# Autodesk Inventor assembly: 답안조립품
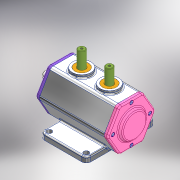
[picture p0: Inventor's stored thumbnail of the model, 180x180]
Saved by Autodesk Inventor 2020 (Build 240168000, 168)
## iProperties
Created: 2021-06
Part Number: 답안조립품
Document SubType Name: Assembly
Designer: Windows7
Author: Windows7
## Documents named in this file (11)
- C:\Users\Windows7\Desktop\710606V1005\답안조립품.iam
- C:\Users\Windows7\Desktop\710606V1005\본체.ipt
- C:\Users\Windows7\Desktop\710606V1005\뒷커버.ipt
- C:\Users\Windows7\Desktop\710606V1005\앞커버.ipt
- C:\Users\Windows7\Desktop\710606V1005\부시.ipt
- C:\Users\Windows7\Desktop\710606V1005\베어링 6203.ipt
- C:\Users\Windows7\Desktop\710606V1005\베어링 6302.ipt
- C:\Users\Windows7\Desktop\710606V1005\오일실.ipt
- C:\Users\Windows7\Desktop\710606V1005\편심축.ipt
- C:\Users\Windows7\Desktop\710606V1005\슬라이더.ipt
- C:\Users\Windows7\Desktop\710606V1005\볼트 M4.ipt
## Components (10 placed, 3 different names)
1. 7-베어링 6203:1
2. 8-오일실:1
3. 9-M4-소켓머리:1
4. 9-M4-소켓머리:3
5. 9-M4-소켓머리:4
6. 9-M4-소켓머리:5
7. 9-M4-소켓머리:2
8. 9-M4-소켓머리:6
9. 9-M4-소켓머리:7
10. 9-M4-소켓머리:8
